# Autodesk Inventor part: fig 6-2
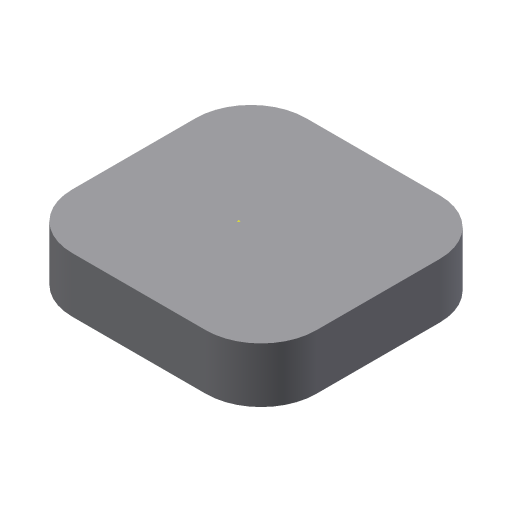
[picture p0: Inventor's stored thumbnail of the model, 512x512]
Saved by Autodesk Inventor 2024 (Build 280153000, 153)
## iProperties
Created: 2004-05
Part Number: fig 6-2
Document SubType Name: Modeling
Designer: CADCIM Technologies
Manufacturer: Standard
Standards Organization: Custom
Density: 1 g/cm^3
Material: Generic
Appearance: Default
Author: CADCIM Technologies
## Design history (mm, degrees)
sketch "Sketch1"
  geometry: L1 (0, 0)-(44.293, 0); L2 (44.293, 0)-(44.293, 42.442); L3 (44.293, 42.442)-(0, 42.442); L4 (0, 42.442)-(0, 0)
  constraints: 8 end point, 2 parallel, 1 horizontal, 1 perpendicular
extrude "Extrusion1" new body sketch "Sketch1" distance "d0" = 10; taper "d1" = 0 deg
fillet "Fillet1" dims "d2" = 10
sketch "Sketch2"
  geometry: 1 further point
sketch "Sketch3"
  geometry: L1 (10, 42.442)-(34.293, 42.442) reference; L2 (0, 10)-(0, 32.442) reference; L3 (34.293, 0)-(10, 0) reference; L4 (44.293, 32.442)-(44.293, 10) reference; A1 r 10 centre (34.293, 32.442) between (44.293, 32.442) and (34.293, 42.442) reference; A2 r 10 centre (10, 32.442) between (10, 42.442) and (0, 32.442) reference; A3 r 10 centre (10, 10) between (0, 10) and (10, 0) reference; A4 r 10 centre (34.293, 10) between (34.293, 0) and (44.293, 10) reference; 1 further point
workpoint "Work Point1"
body "Solid1"
